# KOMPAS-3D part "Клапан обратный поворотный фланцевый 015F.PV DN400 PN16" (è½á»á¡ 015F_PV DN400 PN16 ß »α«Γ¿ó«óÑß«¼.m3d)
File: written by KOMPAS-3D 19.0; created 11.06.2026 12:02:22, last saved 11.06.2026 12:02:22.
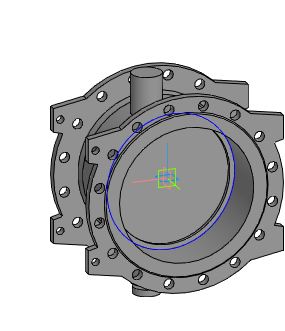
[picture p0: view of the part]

Document properties: Автор: Энергия; Полное имя файла: Z:\3.Личные\kachalov\001_3d для проектировщиков\5.5 Тип 015F.PV Клапан обратный поворотный с двумя эксцентриками\_stp_Клапан 015F.PV DN300-DN1200 с противовесом\Клапан 015F_PV DN400 PN16 с противовесом.m3d

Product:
- Part/product: Клапан обратный поворотный фланцевый 015F.PV DN400 PN16

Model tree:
1. Операция без истории:1
2. Сплайн:1
     Координата Y = 30; Координата Z = 200; Вес = 1; Координата X = 400; Координата Y = 82.661; Координата Z = 200; Вес = 0.333333; Координата X = 400; Координата Y = 82.661; Координата Z = -200; Вес = 0.333333; Координата Y = 30; Координата Z = -200; Вес = 1; Координата X = -400; Координата Y = -22.661; Координата Z = -200; Вес = 0.333333; Координата X = -400; Координата Y = -22.661; Координата Z = 200; Вес = 0.333333; Порядок = 4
